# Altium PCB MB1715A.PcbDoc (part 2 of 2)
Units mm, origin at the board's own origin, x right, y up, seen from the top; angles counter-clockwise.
Board outline 74 x 57 mm, 2 copper layers (Top Layer, Bottom Layer), stack 1.646 mm thick; 54 components, 56 nets, 204 pads, 1587 vias.
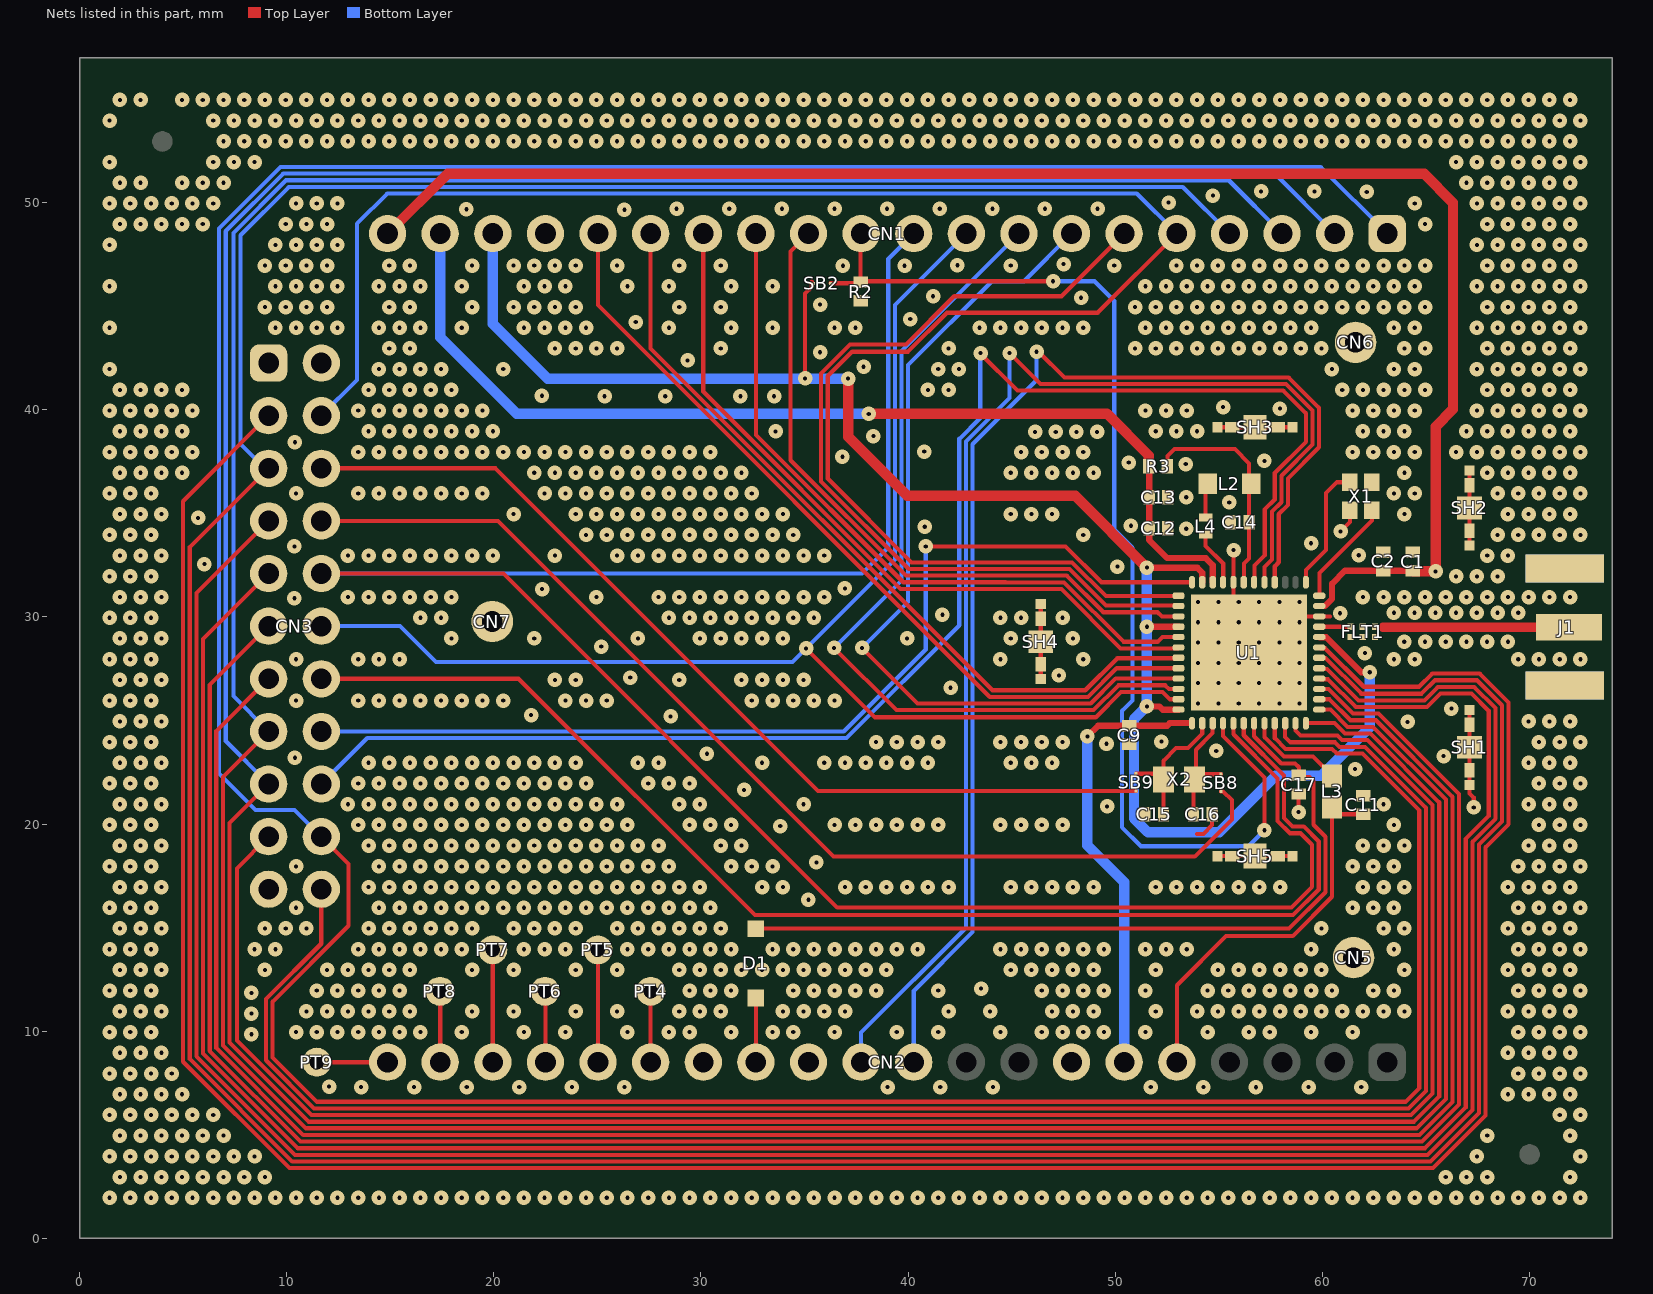
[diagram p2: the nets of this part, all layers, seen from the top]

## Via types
v1: diameter 0.7, hole 0.2, Top Layer to Bottom Layer, 1587 vias

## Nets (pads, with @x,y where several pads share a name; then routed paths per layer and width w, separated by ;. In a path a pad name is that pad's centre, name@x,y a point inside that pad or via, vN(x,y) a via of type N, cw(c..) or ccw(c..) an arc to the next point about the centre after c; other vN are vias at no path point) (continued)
GND: C1.1 C2.1 C9.1 C11.1 C12.2 C13.1 C14.2 C15.2 C16.2 C17.1 CN1.17 CN2.7 CN2.12 CN2.14 CN3.1 CN3.2 CN3.21 CN5.1 CN6.1 CN7.1 FLT1.1 FLT1.2 FLT1.3 FLT1.4 J1.2 R2.2 SH1.1 SH2.1 SH3.1 SH4.1 SH5.1 U1.22 U1.32 U1.49 X1.2 X1.4 | length 32.7
  Top Layer w0.2: SH4.1@46.4,26.99 SH4.1@46.4,27.7 SH4.1@46.4,28.8 SH4.1@46.4,29.9 SH4.1@46.4,30.61 ; 53.95,19.525 54.25,19.525 54.675,19.95 C16.2@54.675,20.475 ; SH5.1@54.94,18.45 SH5.1@56.75,18.45 SH5.1@58.56,18.45 ; SH3.1@54.94,39.15 SH3.1@56.75,39.15 SH3.1@58.56,39.15 ; U1.32@55.7,31.669 55.7,29.032 56.461,28.27 58.21,30.019 60.36,30.019 ; U1.32@55.712,31.669 v1(55.712,33.22) ; v1(58.85,20.575) C17.1@58.85,21.45 ; v1(60.875,34.125) 61.325,34.575 X1.2@61.325,35.15 ; SH1.1@67.1,25.51 SH1.1@67.1,24.8 SH1.1@67.1,23.7 SH1.1@67.1,22.6 SH1.1@67.1,21.89 67.1,21.475 67.3,21.275 v1(67.3,20.8) ; SH2.1@67.1,33.45 SH2.1@67.1,34.16 SH2.1@67.1,35.26 SH2.1@67.1,36.36 SH2.1@67.1,37.07
  other v1: 1.452,1.956 2.452,1.956 3.452,1.956 4.452,1.956 5.452,1.956 6.452,1.956 7.452,1.956 8.452,1.956 9.452,1.956 10.452,1.956 11.452,1.956 12.452,1.956 13.452,1.956 14.452,1.956 15.452,1.956 16.452,1.956 17.452,1.956 18.452,1.956 19.452,1.956 20.452,1.956 21.452,1.956 22.452,1.956 23.452,1.956 24.452,1.956 25.452,1.956 26.452,1.956 27.452,1.956 28.452,1.956 29.452,1.956 30.452,1.956 31.452,1.956 32.452,1.956 33.452,1.956 34.452,1.956 35.452,1.956 36.452,1.956 37.452,1.956 38.452,1.956 39.452,1.956 40.452,1.956 41.452,1.956 42.452,1.956 43.452,1.956 44.452,1.956 45.452,1.956 46.452,1.956 47.452,1.956 48.452,1.956 49.452,1.956 50.452,1.956 51.452,1.956 52.452,1.956 53.452,1.956 54.452,1.956 55.452,1.956 56.452,1.956 57.452,1.956 58.452,1.956 59.452,1.956 60.452,1.956 61.452,1.956 62.452,1.956 63.452,1.956 64.452,1.956 65.452,1.956 66.452,1.956 67.452,1.956 68.452,1.956 69.452,1.956 70.452,1.956 71.452,1.956 72.452,1.956 1.952,2.956 2.952,2.956 3.952,2.956 4.952,2.956 5.952,2.956 6.952,2.956 7.952,2.956 8.952,2.956 65.952,2.956 66.952,2.956 67.952,2.956 71.952,2.956 1.452,3.956 2.452,3.956 3.452,3.956 4.452,3.956 5.452,3.956 6.452,3.956 7.452,3.956 8.452,3.956 67.452,3.956 72.452,3.956 1.952,4.956 2.952,4.956 3.952,4.956 4.952,4.956 5.952,4.956 6.952,4.956 67.952,4.956 71.952,4.956 1.452,5.956 2.452,5.956 3.452,5.956 4.452,5.956 5.452,5.956 6.452,5.956 71.452,5.956 72.452,5.956 1.952,6.956 2.952,6.956 3.952,6.956 4.952,6.956 68.952,6.956 69.952,6.956 70.952,6.956 71.952,6.956 13.59,7.3 16.15,7.3 18.69,7.3 21.23,7.3 23.77,7.3 26.308,7.298 39.01,7.3 41.55,7.3 44.09,7.3 51.71,7.3 54.25,7.3 56.785,7.295 59.33,7.3 61.87,7.3 12.05,7.325 1.452,7.956 2.452,7.956 3.452,7.956 4.452,7.956 69.452,7.956 70.452,7.956 71.452,7.956 72.452,7.956 1.952,8.956 2.952,8.956 3.952,8.956 68.952,8.956 69.952,8.956 70.952,8.956 71.952,8.956 8.3,9.85 1.452,9.956 2.452,9.956 3.452,9.956 10.452,9.956 11.452,9.956 12.452,9.956 13.452,9.956 14.452,9.956 15.452,9.956 16.452,9.956 18.452,9.956 21.452,9.956 23.452,9.956 26.452,9.956 28.452,9.956 29.452,9.956 31.452,9.956 33.452,9.956 34.452,9.956 36.452,9.956 39.452,9.956 41.452,9.956 44.452,9.956 46.452,9.956 47.452,9.956 48.452,9.956 49.452,9.956 51.452,9.956 54.452,9.956 56.452,9.956 57.452,9.956 59.452,9.956 61.452,9.956 69.452,9.956 70.452,9.956 71.452,9.956 72.452,9.956 8.3,10.85 1.952,10.956 2.952,10.956 3.952,10.956 10.952,10.956 11.952,10.956 12.952,10.956 13.952,10.956 14.952,10.956 15.952,10.956 18.952,10.956 20.952,10.956 23.952,10.956 25.952,10.956 28.952,10.956 29.952,10.956 30.952,10.956 33.952,10.956 34.952,10.956 35.952,10.956 36.952,10.956 41.952,10.956 43.952,10.956 46.952,10.956 47.952,10.956 48.952,10.956 51.952,10.956 53.952,10.956 54.952,10.956 55.952,10.956 56.952,10.956 57.952,10.956 58.952,10.956 59.952,10.956 60.952,10.956 61.952,10.956 62.952,10.956 63.952,10.956 68.952,10.956 69.952,10.956 70.952,10.956 71.952,10.956 8.3,11.85 1.452,11.956 2.452,11.956 3.452,11.956 11.452,11.956 12.452,11.956 13.452,11.956 14.452,11.956 15.452,11.956 29.452,11.956 30.452,11.956 31.452,11.956 34.452,11.956 35.452,11.956 36.452,11.956 37.452,11.956 38.452,11.956 41.452,11.956 46.452,11.956 47.452,11.956 48.452,11.956 49.452,11.956 51.452,11.956 54.452,11.956 55.452,11.956 56.452,11.956 57.452,11.956 58.452,11.956 59.452,11.956 60.452,11.956 62.452,11.956 63.452,11.956 69.452,11.956 70.452,11.956 71.452,11.956 72.452,11.956 43.518,12.057 1.952,12.956 2.952,12.956 3.952,12.956 8.952,12.956 11.952,12.956 12.952,12.956 13.952,12.956 14.952,12.956 15.952,12.956 18.952,12.956 20.952,12.956 23.952,12.956 25.952,12.956 28.952,12.956 29.952,12.956 30.952,12.956 31.952,12.956 32.952,12.956 33.952,12.956 34.952,12.956 35.952,12.956 36.952,12.956 37.952,12.956 38.952,12.956 44.952,12.956 45.952,12.956 46.952,12.956 47.952,12.956 48.952,12.956 51.952,12.956 54.952,12.956 55.952,12.956 56.952,12.956 57.952,12.956 58.952,12.956 59.952,12.956 63.952,12.956 68.952,12.956 69.952,12.956 70.952,12.956 71.952,12.956 1.452,13.956 2.452,13.956 3.452,13.956 8.452,13.956 9.452,13.956 13.452,13.956 14.452,13.956 15.452,13.956 16.452,13.956 17.452,13.956 18.452,13.956 21.452,13.956 22.452,13.956 23.452,13.956 26.452,13.956 27.452,13.956 28.452,13.956 29.452,13.956 30.452,13.956 31.452,13.956 33.452,13.956 34.452,13.956 35.452,13.956 36.452,13.956 37.452,13.956 38.452,13.956 39.452,13.956 40.452,13.956 44.452,13.956 45.452,13.956 46.452,13.956 47.452,13.956 48.452,13.956 49.452,13.956 51.452,13.956 52.452,13.956 53.452,13.956 59.452,13.956 63.452,13.956 69.452,13.956 70.452,13.956 71.452,13.956 72.452,13.956 1.952,14.956 2.952,14.956 3.952,14.956 8.952,14.956 9.952,14.956 10.952,14.956 13.952,14.956 14.952,14.956 15.952,14.956 16.952,14.956 17.952,14.956 18.952,14.956 20.952,14.956 21.952,14.956 22.952,14.956 23.952,14.956 25.952,14.956 26.952,14.956 27.952,14.956 28.952,14.956 29.952,14.956 30.952,14.956 59.952,14.956 62.952,14.956 63.952,14.956 68.952,14.956 69.952,14.956 70.952,14.956 71.952,14.956 1.452,15.956 2.452,15.956 3.452,15.956 10.452,15.956 14.452,15.956 15.452,15.956 16.452,15.956 17.452,15.956 18.452,15.956 19.452,15.956 20.452,15.956 21.452,15.956 22.452,15.956 23.452,15.956 24.452,15.956 25.452,15.956 26.452,15.956 27.452,15.956 28.452,15.956 29.452,15.956 30.452,15.956 61.452,15.956 62.452,15.956 63.452,15.956 69.452,15.956 70.452,15.956 71.452,15.956 72.452,15.956 35.182,16.343 1.952,16.956 2.952,16.956 3.952,16.956 13.952,16.956 14.952,16.956 15.952,16.956 16.952,16.956 17.952,16.956 18.952,16.956 19.952,16.956 20.952,16.956 21.952,16.956 22.952,16.956 23.952,16.956 24.952,16.956 25.952,16.956 26.952,16.956 27.952,16.956 28.952,16.956 29.952,16.956 32.952,16.956 33.952,16.956 36.952,16.956 37.952,16.956 38.952,16.956 39.952,16.956 40.952,16.956 41.952,16.956 44.952,16.956 45.952,16.956 46.952,16.956 47.952,16.956 48.952,16.956 51.952,16.956 52.952,16.956 53.952,16.956 54.952,16.956 55.952,16.956 56.952,16.956 57.952,16.956 61.952,16.956 62.952,16.956 63.952,16.956 68.952,16.956 69.952,16.956 70.952,16.956 71.952,16.956 1.452,17.956 2.452,17.956 3.452,17.956 10.452,17.956 14.452,17.956 15.452,17.956 16.452,17.956 17.452,17.956 18.452,17.956 19.452,17.956 20.452,17.956 21.452,17.956 22.452,17.956 23.452,17.956 24.452,17.956 25.452,17.956 26.452,17.956 27.452,17.956 28.452,17.956 31.452,17.956 32.452,17.956 33.452,17.956 61.452,17.956 62.452,17.956 63.452,17.956 69.452,17.956 70.452,17.956 71.452,17.956 72.452,17.956 35.575,18.15 1.952,18.956 2.952,18.956 3.952,18.956 13.952,18.956 14.952,18.956 15.952,18.956 16.952,18.956 17.952,18.956 18.952,18.956 19.952,18.956 20.952,18.956 21.952,18.956 22.952,18.956 23.952,18.956 24.952,18.956 25.952,18.956 26.952,18.956 27.952,18.956 30.952,18.956 31.952,18.956 61.952,18.956 62.952,18.956 63.952,18.956 69.952,18.956 70.952,18.956 71.952,18.956 33.825,19.9 1.452,19.956 2.452,19.956 3.452,19.956 13.452,19.956 14.452,19.956 15.452,19.956 16.452,19.956 17.452,19.956 18.452,19.956 19.452,19.956 20.452,19.956 21.452,19.956 22.452,19.956 23.452,19.956 24.452,19.956 25.452,19.956 26.452,19.956 29.452,19.956 30.452,19.956 31.452,19.956 36.452,19.956 37.452,19.956 38.452,19.956 39.452,19.956 40.452,19.956 41.452,19.956 44.452,19.956 45.452,19.956 46.452,19.956 47.452,19.956 63.452,19.956 70.452,19.956 71.452,19.956 72.452,19.956 49.6,20.85 1.952,20.956 2.952,20.956 3.952,20.956 12.952,20.956 13.952,20.956 14.952,20.956 15.952,20.956 16.952,20.956 17.952,20.956 18.952,20.956 19.952,20.956 20.952,20.956 21.952,20.956 22.952,20.956 23.952,20.956 24.952,20.956 25.952,20.956 28.952,20.956 29.952,20.956 34.952,20.956 62.952,20.956 69.952,20.956 70.952,20.956 71.952,20.956 32.082,21.643 1.452,21.956 2.452,21.956 3.452,21.956 13.452,21.956 14.452,21.956 15.452,21.956 16.452,21.956 17.452,21.956 18.452,21.956 19.452,21.956 20.452,21.956 21.452,21.956 22.452,21.956 23.452,21.956 24.452,21.956 27.452,21.956 28.452,21.956 29.452,21.956 70.452,21.956 71.452,21.956 72.452,21.956 61.575,22.65 1.952,22.956 2.952,22.956 3.952,22.956 13.952,22.956 14.952,22.956 15.952,22.956 16.952,22.956 17.952,22.956 18.952,22.956 19.952,22.956 20.952,22.956 21.952,22.956 22.952,22.956 23.952,22.956 26.952,22.956 27.952,22.956 32.952,22.956 35.952,22.956 36.952,22.956 37.952,22.956 38.952,22.956 39.952,22.956 40.952,22.956 44.952,22.956 45.952,22.956 46.952,22.956 69.952,22.956 70.952,22.956 71.952,22.956 10.4,23.2 65.85,23.275 30.282,23.393 54.875,23.525 49.575,23.875 1.452,23.956 2.452,23.956 3.452,23.956 38.452,23.956 39.452,23.956 40.452,23.956 41.452,23.956 44.452,23.956 45.452,23.956 46.452,23.956 47.452,23.956 70.452,23.956 71.452,23.956 72.452,23.956 52.225,23.975 64.11,24.931 1.952,24.956 2.952,24.956 3.952,24.956 69.952,24.956 70.952,24.956 71.952,24.956 28.532,25.193 21.801,25.26 66.225,25.575 54,25.82 54.98,25.82 55.96,25.82 56.94,25.82 57.92,25.82 58.9,25.82 1.452,25.956 2.452,25.956 3.452,25.956 10.452,25.956 13.452,25.956 14.452,25.956 15.452,25.956 16.452,25.956 17.452,25.956 18.452,25.956 19.452,25.956 20.452,25.956 23.452,25.956 24.452,25.956 25.452,25.956 32.452,25.956 33.452,25.956 34.452,25.956 35.452,25.956 36.452,25.956 42.05,26.575 54,26.8 54.98,26.8 55.96,26.8 56.94,26.8 57.92,26.8 58.9,26.8 1.952,26.956 2.952,26.956 3.952,26.956 22.952,26.956 23.952,26.956 28.952,26.956 31.952,26.956 32.952,26.956 33.952,26.956 34.952,26.956 26.582,27.068 47.275,27.175 54,27.78 54.98,27.78 55.96,27.78 56.94,27.78 57.92,27.78 58.9,27.78 1.452,27.956 2.452,27.956 3.452,27.956 10.452,27.956 13.452,27.956 14.452,27.956 15.452,27.956 44.452,27.956 48.452,27.956 63.452,27.956 64.452,27.956 69.452,27.956 70.452,27.956 71.452,27.956 72.452,27.956 62.05,28.25 25.182,28.568 54,28.76 54.98,28.76 55.96,28.76 56.94,28.76 57.92,28.76 58.9,28.76 63.95,28.8 64.95,28.8 65.95,28.8 66.95,28.8 67.95,28.8 68.95,28.8 1.952,28.956 2.952,28.956 3.952,28.956 17.952,28.956 21.952,28.956 26.952,28.956 29.952,28.956 30.952,28.956 31.952,28.956 32.952,28.956 33.952,28.956 39.952,28.956 44.952,28.956 47.952,28.956 54,29.74 54.98,29.74 55.96,29.74 56.94,29.74 57.92,29.74 58.9,29.74 1.452,29.956 2.452,29.956 3.452,29.956 16.452,29.956 17.452,29.956 28.452,29.956 29.452,29.956 30.452,29.956 31.452,29.956 32.452,29.956 33.452,29.956 34.452,29.956 35.452,29.956 44.452,29.956 45.452,29.956 47.452,29.956 41.65,30.1 60.85,30.175 63.45,30.2 64.45,30.2 65.45,30.2 66.45,30.2 67.45,30.2 68.45,30.2 69.45,30.2 54,30.72 54.98,30.72 55.96,30.72 56.94,30.72 57.92,30.72 58.9,30.72 10.375,30.9 1.952,30.956 2.952,30.956 3.952,30.956 12.952,30.956 13.952,30.956 14.952,30.956 15.952,30.956 16.952,30.956 17.952,30.956 24.952,30.956 27.952,30.956 28.952,30.956 29.952,30.956 30.952,30.956 31.952,30.956 32.952,30.956 33.952,30.956 34.952,30.956 35.952,30.956 61.952,30.956 62.952,30.956 63.952,30.956 64.952,30.956 65.952,30.956 66.952,30.956 67.952,30.956 68.952,30.956 69.952,30.956 70.952,30.956 71.952,30.956 22.332,31.343 36.95,31.375 1.452,31.956 2.452,31.956 3.452,31.956 66.452,31.956 67.452,31.956 68.452,31.956 50.1,32.425 6.025,32.55 1.952,32.956 2.952,32.956 3.952,32.956 12.952,32.956 13.952,32.956 14.952,32.956 15.952,32.956 16.952,32.956 17.952,32.956 18.952,32.956 19.952,32.956 22.952,32.956 25.952,32.956 26.952,32.956 27.952,32.956 28.952,32.956 29.952,32.956 30.952,32.956 31.952,32.956 32.952,32.956 33.952,32.956 34.952,32.956 35.952,32.956 61.75,32.975 67.952,32.956 68.952,32.956 10.375,33.4 59.45,33.55 1.452,33.956 2.452,33.956 3.452,33.956 24.452,33.956 25.452,33.956 26.452,33.956 27.452,33.956 28.452,33.956 29.452,33.956 30.452,33.956 31.452,33.956 32.452,33.956 33.452,33.956 34.452,33.956 48.452,33.956 68.452,33.956 69.452,33.956 70.452,33.956 71.452,33.956 72.452,33.956 53.425,34.25 40.8,34.35 50.75,34.4 5.725,34.775 1.952,34.956 2.952,34.956 3.952,34.956 20.952,34.956 23.952,34.956 24.952,34.956 25.952,34.956 26.952,34.956 27.952,34.956 28.952,34.956 29.952,34.956 30.952,34.956 31.952,34.956 32.952,34.956 33.952,34.956 44.952,34.956 45.952,34.956 46.952,34.956 63.952,34.956 68.952,34.956 69.952,34.956 70.952,34.956 71.952,34.956 55.5,35.525 53.425,35.775 1.452,35.956 2.452,35.956 3.452,35.956 10.452,35.956 13.452,35.956 14.452,35.956 15.452,35.956 16.452,35.956 17.452,35.956 18.452,35.956 19.452,35.956 22.452,35.956 23.452,35.956 24.452,35.956 25.452,35.956 26.452,35.956 27.452,35.956 28.452,35.956 29.452,35.956 30.452,35.956 31.452,35.956 32.452,35.956 63.452,35.956 64.452,35.956 68.452,35.956 69.452,35.956 70.452,35.956 71.452,35.956 72.452,35.956 1.952,36.956 2.952,36.956 3.952,36.956 4.952,36.956 21.952,36.956 22.952,36.956 23.952,36.956 24.952,36.956 25.952,36.956 26.952,36.956 27.952,36.956 28.952,36.956 29.952,36.956 30.952,36.956 31.952,36.956 44.952,36.956 45.952,36.956 46.952,36.956 47.952,36.956 48.952,36.956 63.952,36.956 67.952,36.956 68.952,36.956 69.952,36.956 70.952,36.956 71.952,36.956 53.4,37.375 50.65,37.45 57.2,37.525 36.825,37.725 1.452,37.956 2.452,37.956 3.452,37.956 4.452,37.956 5.452,37.956 13.452,37.956 14.452,37.956 15.452,37.956 16.452,37.956 17.452,37.956 18.452,37.956 19.452,37.956 20.452,37.956 21.452,37.956 22.452,37.956 23.452,37.956 24.452,37.956 25.452,37.956 26.452,37.956 27.452,37.956 28.452,37.956 29.452,37.956 30.452,37.956 45.452,37.956 46.452,37.956 47.452,37.956 48.452,37.956 61.452,37.956 62.452,37.956 63.452,37.956 64.452,37.956 66.452,37.956 67.452,37.956 68.452,37.956 69.452,37.956 70.452,37.956 71.452,37.956 72.452,37.956 40.775,37.975 10.4,38.425 38.325,38.725 33.6,38.95 46.125,38.925 47.125,38.925 48.125,38.925 49.125,38.925 1.952,38.956 2.952,38.956 3.952,38.956 4.952,38.956 13.952,38.956 14.952,38.956 15.952,38.956 16.952,38.956 17.952,38.956 18.952,38.956 19.952,38.956 51.952,38.956 52.952,38.956 53.952,38.956 61.952,38.956 62.952,38.956 63.952,38.956 66.952,38.956 67.952,38.956 68.952,38.956 69.952,38.956 70.952,38.956 71.952,38.956 1.452,39.956 2.452,39.956 3.452,39.956 4.452,39.956 5.452,39.956 13.452,39.956 14.452,39.956 15.452,39.956 16.452,39.956 17.452,39.956 18.452,39.956 19.452,39.956 51.452,39.956 52.452,39.956 53.452,39.956 61.452,39.956 62.452,39.956 63.452,39.956 64.452,39.956 67.452,39.956 68.452,39.956 69.452,39.956 70.452,39.956 71.452,39.956 72.452,39.956 57.95,40.05 55.2,40.125 25.35,40.65 28.275,40.65 31.9,40.65 33.525,40.65 22.325,40.675 1.952,40.956 2.952,40.956 3.952,40.956 4.952,40.956 13.952,40.956 14.952,40.956 15.952,40.956 16.952,40.956 17.952,40.956 40.952,40.956 41.952,40.956 60.952,40.956 61.952,40.956 62.952,40.956 63.952,40.956 64.952,40.956 67.952,40.956 68.952,40.956 69.952,40.956 70.952,40.956 71.952,40.956 1.452,41.956 14.452,41.956 15.452,41.956 16.452,41.956 17.452,41.956 20.452,41.956 41.452,41.956 42.452,41.956 60.452,41.956 63.452,41.956 64.452,41.956 67.452,41.956 68.452,41.956 69.452,41.956 70.452,41.956 71.452,41.956 72.452,41.956 37.85,42.075 29.35,42.375 35.75,42.775 14.952,42.956 15.952,42.956 22.952,42.956 23.952,42.956 24.952,42.956 25.952,42.956 30.952,42.956 41.952,42.956 50.952,42.956 51.952,42.956 52.952,42.956 53.952,42.956 54.952,42.956 55.952,42.956 56.952,42.956 57.952,42.956 58.952,42.956 59.952,42.956 63.952,42.956 64.952,42.956 67.952,42.956 68.952,42.956 69.952,42.956 70.952,42.956 71.952,42.956 1.452,43.956 9.452,43.956 10.452,43.956 11.452,43.956 12.452,43.956 14.452,43.956 15.452,43.956 16.452,43.956 18.452,43.956 21.452,43.956 22.452,43.956 23.452,43.956 24.452,43.956 28.452,43.956 31.452,43.956 33.452,43.956 36.452,43.956 37.452,43.956 43.452,43.956 44.452,43.956 45.452,43.956 46.452,43.956 47.452,43.956 48.452,43.956 51.452,43.956 52.452,43.956 53.452,43.956 54.452,43.956 55.452,43.956 56.452,43.956 57.452,43.956 58.452,43.956 59.452,43.956 63.452,43.956 64.452,43.956 67.452,43.956 68.452,43.956 69.452,43.956 70.452,43.956 71.452,43.956 72.452,43.956 26.85,44.225 40.1,44.375 8.952,44.956 9.952,44.956 10.952,44.956 11.952,44.956 14.952,44.956 15.952,44.956 18.952,44.956 20.952,44.956 21.952,44.956 22.952,44.956 23.952,44.956 28.952,44.956 30.952,44.956 50.952,44.956 51.952,44.956 52.952,44.956 53.952,44.956 54.952,44.956 55.952,44.956 56.952,44.956 57.952,44.956 58.952,44.956 59.952,44.956 60.952,44.956 61.952,44.956 62.952,44.956 63.952,44.956 64.952,44.956 67.952,44.956 68.952,44.956 69.952,44.956 70.952,44.956 71.952,44.956 35.75,45.075 48.35,45.4 41.2,45.475 1.452,45.956 9.452,45.956 10.452,45.956 11.452,45.956 12.452,45.956 14.452,45.956 15.452,45.956 16.452,45.956 18.452,45.956 21.452,45.956 22.452,45.956 23.452,45.956 26.452,45.956 28.452,45.956 31.452,45.956 33.452,45.956 51.452,45.956 52.452,45.956 53.452,45.956 54.452,45.956 55.452,45.956 56.452,45.956 57.452,45.956 58.452,45.956 59.452,45.956 60.452,45.956 61.452,45.956 62.452,45.956 63.452,45.956 64.452,45.956 67.452,45.956 68.452,45.956 69.452,45.956 70.452,45.956 71.452,45.956 72.452,45.956 36.85,46.95 39.825,46.95 8.952,46.956 9.952,46.956 10.952,46.956 11.952,46.956 14.952,46.956 15.952,46.956 18.952,46.956 20.952,46.956 21.952,46.956 22.952,46.956 23.952,46.956 25.952,46.956 28.952,46.956 30.952,46.956 42.375,46.975 44.952,46.956 49.952,46.956 52.952,46.956 53.952,46.956 54.952,46.956 55.952,46.956 56.952,46.956 57.952,46.956 58.952,46.956 59.952,46.956 60.952,46.956 61.952,46.956 62.952,46.956 63.952,46.956 64.952,46.956 67.952,46.956 68.952,46.956 69.952,46.956 70.952,46.956 71.952,46.956 47.5,47.025 1.452,47.956 9.452,47.956 10.452,47.956 11.452,47.956 12.452,47.956 67.452,47.956 68.452,47.956 69.452,47.956 70.452,47.956 71.452,47.956 72.452,47.956 1.952,48.956 2.952,48.956 3.952,48.956 4.952,48.956 5.952,48.956 9.952,48.956 10.952,48.956 11.952,48.956 64.952,48.956 67.952,48.956 68.952,48.956 69.952,48.956 70.952,48.956 71.952,48.956 26.3,49.65 18.675,49.675 28.825,49.7 31.365,49.7 33.905,49.7 36.445,49.7 38.985,49.7 41.525,49.7 44.065,49.7 46.605,49.7 49.145,49.7 1.452,49.956 2.452,49.956 3.452,49.956 4.452,49.956 5.452,49.956 6.452,49.956 10.452,49.956 11.452,49.956 12.452,49.956 64.452,49.956 67.452,49.956 68.452,49.956 69.452,49.956 70.452,49.956 71.452,49.956 72.452,49.956 52.575,50 54.71,50.335 62.135,50.51 57.035,50.535 59.61,50.535 1.952,50.956 2.952,50.956 4.952,50.956 5.952,50.956 6.952,50.956 66.952,50.956 67.952,50.956 68.952,50.956 69.952,50.956 70.952,50.956 71.952,50.956 1.452,51.956 6.452,51.956 7.452,51.956 8.452,51.956 66.452,51.956 67.452,51.956 68.452,51.956 69.452,51.956 70.452,51.956 71.452,51.956 72.452,51.956 6.952,52.956 7.952,52.956 8.952,52.956 9.952,52.956 10.952,52.956 11.952,52.956 12.952,52.956 13.952,52.956 14.952,52.956 15.952,52.956 16.952,52.956 17.952,52.956 18.952,52.956 19.952,52.956 20.952,52.956 21.952,52.956 22.952,52.956 23.952,52.956 24.952,52.956 25.952,52.956 26.952,52.956 27.952,52.956 28.952,52.956 29.952,52.956 30.952,52.956 31.952,52.956 32.952,52.956 33.952,52.956 34.952,52.956 35.952,52.956 36.952,52.956 37.952,52.956 38.952,52.956 39.952,52.956 40.952,52.956 41.952,52.956 42.952,52.956 43.952,52.956 44.952,52.956 45.952,52.956 46.952,52.956 47.952,52.956 48.952,52.956 49.952,52.956 50.952,52.956 51.952,52.956 52.952,52.956 53.952,52.956 54.952,52.956 55.952,52.956 56.952,52.956 57.952,52.956 58.952,52.956 59.952,52.956 60.952,52.956 61.952,52.956 62.952,52.956 63.952,52.956 64.952,52.956 65.952,52.956 66.952,52.956 67.952,52.956 68.952,52.956 69.952,52.956 70.952,52.956 71.952,52.956 1.452,53.956 6.452,53.956 7.452,53.956 8.452,53.956 9.452,53.956 10.452,53.956 11.452,53.956 12.452,53.956 13.452,53.956 14.452,53.956 15.452,53.956 16.452,53.956 17.452,53.956 18.452,53.956 19.452,53.956 20.452,53.956 21.452,53.956 22.452,53.956 23.452,53.956 24.452,53.956 25.452,53.956 26.452,53.956 27.452,53.956 28.452,53.956 29.452,53.956 30.452,53.956 31.452,53.956 32.452,53.956 33.452,53.956 34.452,53.956 35.452,53.956 36.452,53.956 37.452,53.956 38.452,53.956 39.452,53.956 40.452,53.956 41.452,53.956 42.452,53.956 43.452,53.956 44.452,53.956 45.452,53.956 46.452,53.956 47.452,53.956 48.452,53.956 49.452,53.956 50.452,53.956 51.452,53.956 52.452,53.956 53.452,53.956 54.452,53.956 55.452,53.956 56.452,53.956 57.452,53.956 58.452,53.956 59.452,53.956 60.452,53.956 61.452,53.956 62.452,53.956 63.452,53.956 64.452,53.956 65.452,53.956 66.452,53.956 67.452,53.956 68.452,53.956 69.452,53.956 70.452,53.956 71.452,53.956 72.452,53.956 1.952,54.956 2.952,54.956 4.952,54.956 5.952,54.956 6.952,54.956 7.952,54.956 8.952,54.956 9.952,54.956 10.952,54.956 11.952,54.956 12.952,54.956 13.952,54.956 14.952,54.956 15.952,54.956 16.952,54.956 17.952,54.956 18.952,54.956 19.952,54.956 20.952,54.956 21.952,54.956 22.952,54.956 23.952,54.956 24.952,54.956 25.952,54.956 26.952,54.956 27.952,54.956 28.952,54.956 29.952,54.956 30.952,54.956 31.952,54.956 32.952,54.956 33.952,54.956 34.952,54.956 35.952,54.956 36.952,54.956 37.952,54.956 38.952,54.956 39.952,54.956 40.952,54.956 41.952,54.956 42.952,54.956 43.952,54.956 44.952,54.956 45.952,54.956 46.952,54.956 47.952,54.956 48.952,54.956 49.952,54.956 50.952,54.956 51.952,54.956 52.952,54.956 53.952,54.956 54.952,54.956 55.952,54.956 56.952,54.956 57.952,54.956 58.952,54.956 59.952,54.956 60.952,54.956 61.952,54.956 62.952,54.956 63.952,54.956 64.952,54.956 65.952,54.956 66.952,54.956 67.952,54.956 68.952,54.956 69.952,54.956 70.952,54.956 71.952,54.956
NetC14_1: C14.1 L2.2 R3.2 U1.31 | length 10.7
  Top Layer w0.2: R3.2@52.511,37.27 52.511,37.759 52.852,38.1 55.772,38.1 56.461,37.41 C14.1@56.461,34.57 56.461,32.82 56.212,32.571 U1.31@56.212,31.669
NetC15_1: C15.1 SB9.2 U1.2 X2.1 | length 6.5
  Top Layer w0.2: SB9.2@51,22.425 52.15,22.425 52.325,22.6 52.325,23.05 52.936,23.661 53.511,23.661 54.211,24.361 54.2,24.373 U1.2@54.2,24.872 ; C15.1@52.325,20.475 X2.1@52.325,22.15
NetC16_1: C16.1 SB8.2 U1.3 X2.2 | length 6
  Top Layer w0.2: C16.1@53.775,20.475 53.775,22.016 53.888,22.129 X2.2@53.888,22.461 ; U1.3@54.7,24.872 54.7,24.397 53.888,23.585 X2.2@53.888,22.461 ; SB8.2@55.1,22.4 53.949,22.4 X2.2@53.888,22.461
NetC17_2: C17.2 D1.A U1.7 | length 38.5
  Top Layer w0.2: D1.A@32.65,14.95 34.15,14.95 58.388,14.95 60.141,16.704 60.141,19.384 59.561,19.964 59.561,22.089 59.375,22.275 58.85,22.275 58.862,22.286 58.862,22.739 58.675,22.925 58.012,22.925 56.7,24.237 U1.7@56.7,24.872
NetCN2_15: CN2.15 PT4.1 | length 3.4
  Top Layer w0.2: CN2.15@27.57,8.5 PT4.1@27.57,11.92
NetCN2_16: CN2.16 PT5.1 | length 5.4
  Top Layer w0.2: CN2.16@25.025,8.495 CN2.16@25.03,8.5 ; CN2.16@25.025,8.505 PT5.1@25.025,13.925
NetCN2_17: CN2.17 PT6.1 | length 3.4
  Top Layer w0.2: CN2.17@22.49,8.5 PT6.1@22.49,11.91
NetCN2_18: CN2.18 PT7.1 | length 5.4
  Top Layer w0.2: CN2.18@19.95,8.5 PT7.1@19.95,13.925
NetCN2_19: CN2.19 PT8.1 | length 3.4
  Top Layer w0.2: CN2.19@17.41,8.5 PT8.1@17.41,11.915
NetCN2_20: CN2.20 PT9.1 | length 3.4
  Top Layer w0.2: PT9.1@11.455,8.5 CN2.20@14.87,8.5
NetFLT1_5: FLT1.5 U1.21 | length 1.5
  Top Layer w0.2: U1.21@59.86,29.52 FLT1.5@61.359,29.52
NetFLT1_6: FLT1.6 J1.1 | length 9
  Top Layer w0.45: 62.92,29.5 J1.1@71.9,29.5
NetL2_1: L2.1 L4.1 | length 1.7
  Top Layer w0.2: L4.1@54.361,34.795 54.361,36.32 L2.1@54.461,36.42
NetL3_2: L3.2 U1.8 | length 4.7
  Top Layer w0.2: U1.8@57.2,24.872 57.2,24.19 58.139,23.25 59.55,23.25 60.461,22.339 L3.2@60.461,22.32
NetL4_2: L4.2 U1.33 | length 2.7
  Top Layer w0.2: L4.2@54.361,33.97 54.361,33.42 55.212,32.57 U1.33@55.212,31.669
NetU1_24: U1.24 X1.3 | length 5.2
  Top Layer w0.2: U1.24@59.86,31.019 59.86,32.119 62.386,34.645 X1.3@62.386,35.15
NetU1_25: U1.25 X1.1 | length 6.1
  Top Layer w0.2: U1.25@59.2,31.669 59.2,32.259 60.175,33.234 60.175,35.975 60.7,36.5 X1.1@61.325,36.5
NRST: CN2.13 D1.K | length 3.1
  Top Layer w0.2: CN2.13@32.65,8.5 D1.K@32.65,11.6
PA0: CN1.1 CN3.20 U1.9 | length 183.3
  Top Layer w0.2: CN3.20@11.67,19.39 12.993,18.067 12.993,15.09 9.32,11.417 9.32,8.73 11.46,6.59 64.015,6.59 64.675,7.25 64.675,20.65 61.925,23.4 60.692,23.4 60.468,23.624 58.218,23.624 57.7,24.142 U1.9@57.7,24.872
  Bottom Layer w0.2: CN3.20@11.67,19.39 10.385,20.675 8.5,20.675 6.738,22.437 6.738,48.749 9.705,51.715 59.915,51.715 CN1.1@63.13,48.5
PA1: CN3.22 U1.10 | length 89.2
  Top Layer w0.2: CN3.22@11.67,16.85 11.67,14.22 9,11.55 9,8.597 11.327,6.27 64.148,6.27 64.995,7.117 64.995,20.783 62.053,23.725 60.82,23.725 60.601,23.944 58.456,23.944 58.2,24.2 U1.10@58.2,24.872
PA2: CN3.19 U1.11 | length 92.5
  Top Layer w0.2: CN3.19@9.13,19.39 7.597,17.857 7.597,9.548 11.195,5.95 64.28,5.95 65.315,6.985 65.315,20.915 62.18,24.05 60.948,24.05 60.733,24.264 58.943,24.264 58.7,24.507 U1.11@58.7,24.872
PA3: CN1.2 CN3.17 U1.12 | length 179.4
  Top Layer w0.2: CN3.17@9.13,21.93 7.244,20.044 7.244,9.449 11.062,5.63 64.413,5.63 65.635,6.852 65.635,21.048 62.313,24.37 61.08,24.37 60.578,24.872 U1.12@59.222,24.872
  Bottom Layer w0.2: CN3.17@9.13,21.93 7.058,24.002 7.058,48.616 9.837,51.395 57.695,51.395 CN1.2@60.59,48.5
PA4: CN1.3 CN3.15 U1.13 | length 177.2
  Top Layer w0.2: CN3.15@9.13,24.47 6.924,22.264 6.924,9.316 10.93,5.31 64.545,5.31 65.955,6.72 65.955,21.18 62.445,24.69 61.213,24.69 60.384,25.519 U1.13@59.86,25.519
  Bottom Layer w0.2: CN3.15@9.13,24.47 7.425,26.175 7.425,48.53 9.97,51.075 55.475,51.075 CN1.3@58.05,48.5
PA5: CN3.13 U1.14 | length 104
  Top Layer w0.2: CN3.13@9.13,27.01 6.604,24.484 6.604,9.184 10.797,4.99 64.678,4.99 66.275,6.587 66.275,21.313 62.578,25.01 61.345,25.01 60.336,26.019 U1.14@59.86,26.019
PA6: CN3.11 U1.15 | length 108.4
  Top Layer w0.2: CN3.11@9.13,29.55 6.284,26.704 6.284,9.051 10.665,4.67 64.81,4.67 66.595,6.455 66.595,21.445 62.71,25.33 61.478,25.33 60.289,26.519 U1.15@59.86,26.519
PA7: CN3.9 U1.16 | length 117.1
  Top Layer w0.2: CN3.9@9.13,32.09 5.964,28.924 5.964,8.918 10.532,4.35 64.943,4.35 66.915,6.322 66.915,19.273 68.025,20.383 68.025,25.467 67.192,26.3 65.7,26.3 65.05,25.65 61.61,25.65 60.275,26.985 59.894,26.985 U1.16@59.86,27.019
PA8: CN3.7 U1.17 | length 121.4
  Top Layer w0.2: CN3.7@9.13,34.63 5.644,31.144 5.644,8.786 10.4,4.03 65.075,4.03 67.235,6.19 67.235,19.14 68.345,20.25 68.345,25.6 67.325,26.62 65.567,26.62 64.917,25.97 61.743,25.97 60.228,27.485 59.894,27.485 U1.17@59.86,27.519
PA9: CN1.4 CN3.5 U1.18 | length 187.3
  Top Layer w0.2: CN3.5@9.13,37.17 5.324,33.364 5.324,8.653 10.267,3.71 65.208,3.71 67.555,6.057 67.555,19.008 68.665,20.118 68.665,25.732 67.457,26.94 65.435,26.94 64.785,26.29 61.875,26.29 60.147,28.019 U1.18@59.86,28.019
  Bottom Layer w0.2: CN3.5@9.13,37.17 8.948,37.17 7.769,38.349 7.769,48.421 10.102,50.755 53.255,50.755 CN1.4@55.51,48.5
PA10: CN3.16 U1.36 | length 49.4
  Top Layer w0.2: v1(40.85,33.4) 45.35,33.4 47.601,33.4 49.332,31.669 U1.36@53.712,31.669
  Bottom Layer w0.2: CN3.16@11.67,24.47 36.892,24.47 40.85,28.428 v1(40.85,33.4)
PA11: CN1.5 CN3.4 U1.37 | length 94.9
  Top Layer w0.2: CN1.5@52.97,48.5 49.15,44.68 41.88,44.68 40,42.8 37.303,42.8 36.12,41.617 36.12,36.67 40.16,32.63 47.918,32.63 49.548,31 53.043,31 U1.37@53.063,31.02
  Bottom Layer w0.2: CN3.4@11.67,39.71 13.4,41.44 13.4,48.978 14.858,50.435 51.035,50.435 CN1.5@52.97,48.5
PA12: CN1.6 U1.38 | length 42.4
  Top Layer w0.2: CN1.6@50.43,48.5 47.405,45.475 42.222,45.475 39.894,43.147 37.197,43.147 35.8,41.75 35.8,36.538 40.028,32.31 47.786,32.31 49.553,30.542 U1.38@53.039,30.542 ; U1.38@53.063,30.519 U1.38@53.039,30.542 ; U1.38@53.063,30.521 53.042,30.542 U1.38@53.039,30.542
PA13-JTMS_SWDIO: CN1.12 U1.39 | length 33.2
  Top Layer w0.2: CN1.12@35.19,48.5 34.325,47.635 34.325,37.56 39.895,31.99 47.653,31.99 49.421,30.222 52.043,30.222 52.246,30.019 U1.39@53.063,30.019
PA14-JTCK_SWCLK: CN1.13 U1.41 | length 34.4
  Top Layer w0.2: CN1.13@32.65,48.5 32.65,38.783 39.763,31.67 44.705,31.67 44.714,31.661 47.529,31.661 50.391,28.8 52.052,28.8 52.273,29.021 U1.41@53.052,29.021 U1.41@53.063,29.021
PA15-JTDI: CN1.14 U1.42 | length 35.8
  Top Layer w0.2: CN1.14@30.11,48.5 30.11,40.87 39.639,31.341 47.397,31.341 50.258,28.48 53.023,28.48 U1.42@53.063,28.521 ; U1.42@53.024,28.48 U1.42@53.063,28.519
PB0/AT2: CN2.10 U1.28 | length 60.8
  Top Layer w0.2: v1(46.2,42.797) 46.303,42.797 47.54,41.56 58.37,41.56 59.84,40.09 59.84,38.185 58.335,36.68 58.335,35.399 57.892,34.956 57.892,32.634 57.7,32.443 U1.28@57.7,31.669
  Bottom Layer w0.2: CN2.10@40.27,8.5 40.27,11.94 43.11,14.78 43.11,38.33 46.2,41.42 v1(46.2,42.797)
PB1/AT3: CN2.11 U1.29 | length 62.2
  Top Layer w0.2: v1(44.9,42.735) 46.395,41.24 58.238,41.24 59.52,39.958 59.52,38.317 58.015,36.812 58.015,35.532 57.561,35.078 57.561,32.77 57.2,32.409 U1.29@57.2,31.669
  Bottom Layer w0.2: CN2.11@37.73,8.5 37.73,9.93 42.79,14.99 42.79,38.462 44.9,40.572 v1(44.9,42.735)
PB2: CN3.3 U1.19 | length 130.1
  Top Layer w0.2: CN3.3@9.13,39.71 5,35.58 5,8.525 10.135,3.39 65.34,3.39 67.875,5.925 67.875,18.875 68.985,19.985 68.985,25.865 67.59,27.26 65.302,27.26 64.667,26.625 61.993,26.625 60.133,28.485 59.894,28.485 U1.19@59.86,28.519
PB3-JTDO: CN1.15 U1.43 | length 38.5
  Top Layer w0.2: CN1.15@27.57,48.5 27.57,42.958 44.073,26.455 48.55,26.455 50.093,27.998 U1.43@53.041,27.998
PB4-NJTRST: CN1.16 U1.44 | length 39.9
  Top Layer w0.2: CN1.16@25.03,48.5 25.03,45.045 43.94,26.135 48.682,26.135 50.068,27.521 U1.44@53.052,27.521 U1.44@53.063,27.521
PB5: CN1.7 U1.45 | length 42
  Top Layer w0.2: v1(37.775,28.5) 40.46,25.815 48.815,25.815 50.019,27.019 53.061,27.019 U1.45@53.063,27.021
  Bottom Layer w0.2: v1(37.775,28.5) 40,30.725 40,42.159 44.041,46.2 45.59,46.2 CN1.7@47.89,48.5
PB6: CN1.8 U1.46 | length 42.1
  Top Layer w0.2: v1(36.425,28.5) 39.43,25.495 48.948,25.495 50.148,26.695 52.408,26.695 52.585,26.519 U1.46@53.063,26.519
  Bottom Layer w0.2: v1(36.425,28.5) 39.68,31.755 39.68,42.83 CN1.8@45.35,48.5
PB7: CN1.9 CN3.12 U1.47 | length 67.6
  Top Layer w0.2: v1(35.075,28.475) 38.4,25.15 49.055,25.15 50.28,26.375 52.275,26.375 52.632,26.019 U1.47@53.063,26.019
  Bottom Layer w0.2: CN3.12@11.67,29.55 15.475,29.55 17.2,27.825 34.425,27.825 v1(35.075,28.475) 39.36,32.76 39.36,45.05 CN1.9@42.81,48.5
PB8: CN1.10 CN3.10 U1.5 | length 108.2
  Top Layer w0.2: CN3.10@11.67,32.09 20.46,32.09 36.575,15.975 58.508,15.975 59.501,16.969 59.501,18.999 58.945,19.555 58.428,19.555 57.83,20.153 57.83,22.202 55.7,24.332 U1.5@55.7,24.872
  Bottom Layer w0.2: CN3.10@11.67,32.09 37.776,32.09 39.04,33.354 39.04,47.27 CN1.10@40.27,48.5
PB9: CN3.14 U1.6 | length 63.2
  Top Layer w0.2: CN3.14@11.67,27.01 21.19,27.01 32.6,15.6 50.553,15.6 58.585,15.6 59.821,16.836 59.821,19.154 59.1,19.875 58.56,19.875 58.15,20.285 58.15,22.334 56.2,24.285 U1.6@56.2,24.872
PC14: CN3.6 SB9.1 | length 45.8
  Top Layer w0.2: CN3.6@11.67,37.17 20.08,37.17 35.65,21.6 SB9.1@51,21.6
PC15: CN3.8 SB8.1 | length 53
  Top Layer w0.2: CN3.8@11.67,34.63 20.195,34.63 36.402,18.423 53.838,18.423 55.625,20.21 55.625,21.15 55.2,21.575 SB8.1@55.1,21.575
PE4: CN3.18 U1.30 | length 73.6
  Top Layer w0.2: v1@43.482,42.718 45.28,40.92 58.105,40.92 59.2,39.825 59.2,38.45 57.695,36.945 57.695,35.664 57.211,35.181 57.211,32.97 56.712,32.471 U1.30@56.712,31.669
  Bottom Layer w0.2: CN3.18@11.67,21.93 13.89,24.15 37.025,24.15 42.47,29.595 42.47,38.595 43.482,39.607 v1@43.482,42.718
  other v1: 43.5,42.735
PH3: CN1.11 R2.1 SB2.2 U1.4 | length 55.8
  Top Layer w0.2: SB2.2@36.25,46.1 37.65,46.1 R2.1@37.7,46.15 ; CN1.11@37.73,48.5 37.7,48.47 R2.1@37.7,46.15 ; v1@46.7,46.2 37.75,46.2 R2.1@37.7,46.15 ; U1.4@55.2,24.872 55.2,24.242 57.2,22.242 v1(57.2,19.7)
  Bottom Layer w0.2: v1(47,46.2) 49,46.2 49.95,45.25 49.95,34.21 50.825,33.335 50.825,25.965 50.325,25.465 50.325,19.84 51.24,18.925 56.425,18.925 v1(57.2,19.7)
VBAT: C9.2 CN2.6 U1.1 | length 21.8
  Top Layer w0.3: v1(48.65,24.225) 49.169,24.744 C9.2@50.661,24.744 52.503,24.744 52.631,24.872 U1.1@53.7,24.872
  Bottom Layer w0.5: v1(48.65,24.225) 48.65,18.975 50.43,17.195 CN2.6@50.43,8.5
VDD: CN1.18 SB2.1 U1.20 U1.35 U1.40 U1.48 | length 86
  Top Layer w0.2: CN1.18@19.95,48.5 CN1.18@19.95,48.976 ; v1(35.025,41.513) 35.025,45.6 35.35,45.925 35.35,46.175
  Top Layer w0.3: v1@51.525,25.67 52.14,25.67 52.291,25.519 U1.48@53.063,25.519 ; v1@51.525,32.37 53.961,32.37 54.2,32.132 U1.35@54.2,31.669 ; v1(51.527,29.519) U1.40@53.063,29.519 ; U1.20@59.86,29.019 60.181,29.019 61.875,27.325 v1@62.258,27.325
  Top Layer w0.5: v1(37.1,41.5) 37.1,38.687 39.947,35.84 48.06,35.84 v1(51.525,32.375)
  Bottom Layer w0.5: CN1.18@19.95,48.5 19.95,44.15 22.6,41.5 v1(37.1,41.5) ; v1(51.525,32.375) v1(51.525,25.675) 50.9,25.05 50.9,20.275 51.575,19.6 55.015,19.6 57.751,22.336 59.952,22.336 62.283,24.667 v1(62.283,27.325)
VDDA: C11.2 CN2.5 L3.1 | length 19
  Top Layer w0.2: CN2.5@52.97,8.5 52.97,12.216 55.347,14.593 58.568,14.593 60.461,16.486 L3.1@60.461,20.82 60.811,20.47 C11.2@61.961,20.47
VDDRF: C1.2 C2.2 CN1.20 U1.23 | length 78.1
  Top Layer w0.3: U1.23@59.86,30.519 60.117,30.519 60.461,30.863 60.461,31.595 61.087,32.22 C1.2@64.361,32.22
  Top Layer w0.5: CN1.20@14.87,48.5 14.875,48.505 17.765,51.395 64.905,51.395 66.3,50 66.3,40.025 65.461,39.186 v1(65.461,32.195) 64.386,32.195 C1.2@64.361,32.22 C1.2@64.374,32.22
VDDSMPS: C12.1 C13.2 CN1.19 R3.1 U1.34 | length 50.1
  Top Layer w0.3: R3.1@51.637,37.27 C13.2@51.637,35.77 C12.1@51.637,34.27 51.637,33.705 52.505,32.837 54.363,32.837 54.7,32.5 U1.34@54.7,31.669
  Top Layer w0.5: v1(38.1,39.8) 49.6,39.8 51.611,37.789 R3.1@51.611,37.27
  Bottom Layer w0.5: CN1.19@17.41,48.5 17.41,43.49 21.1,39.8 v1(38.1,39.8)
pads on no net: Cartridge.1 CARTRIDGE.1 CN2.1 CN2.2 CN2.3 CN2.4 Mire_1.1 MIRE_2.1
copper on no net: | length 0
  Bottom Layer w0.5: 55.5,8.49 55.51,8.5

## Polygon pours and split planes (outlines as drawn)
GND on Top Layer "GND_L01_P000" (solid, remove dead copper, pour order 0): 0,0.05 74,0.05 74,56.95 0,56.95
GND on Bottom Layer "GND_L02_P001" (solid, remove dead copper, pour order 1): 0,0.05 74,0.05 74,56.95 0,56.95

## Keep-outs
Keep-Out Layer:
  lines w1.2: 73.973,57 0,57 0,0 74,0 74,57

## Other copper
Top Layer:
  region net NetFLT1_6: 70.3,30.135 69.759,29.594 69.759,29.406 70.3,28.865 70.667,28.865 70.667,30.131 70.671,30.135
  pour cut-out: 59.736,31.545 59.736,24.995 53.186,24.995 53.186,31.545
  region: 60.924,29.795
  region net NetFLT1_6: 62.975,29.725 62.975,29.275 62.8,29.275 62.705,29.37 62.425,29.37 62.425,29.67 62.72,29.67 62.775,29.725

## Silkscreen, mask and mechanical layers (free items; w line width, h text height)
Top Overlay:
  text "GND" at 59.7,44.85 h2
  text "GND" at 17.975,26.925 h2
  text "GND" at 59.7,10.2 h2
Bottom Overlay:
  text "C" at 31.35,40.7 h10
  text "MB1715A" at 33.325,15.65 h2.5
Mechanical Drawing:
  lines w0.2: 37.6,82.452 156.6,82.453 ; 67.6,72.1 67.6,87.452 ; 80.564,95.147 91.193,95.147 111.75,95.147 130.222,95.147 145.395,95.147 157.458,95.147 ; 80.564,100.227 91.193,100.227 111.75,100.227 130.222,100.227 145.395,100.227 157.458,100.227 ; 80.564,105.307 91.193,105.307 111.75,105.307 130.222,105.307 145.395,105.307 157.458,105.307 ; 80.564,110.387 91.193,110.387 111.75,110.387 130.222,110.387 145.395,110.387 157.458,110.387 ; 80.564,115.467 91.193,115.467 111.75,115.467 130.222,115.467 145.395,115.467 157.458,115.467 ; 80.564,120.547 91.193,120.547 111.75,120.547 130.222,120.547 145.395,120.547 157.458,120.547 ; 80.564,125.627 157.458,125.627 ; 90.6,72.1 90.6,87.453 ; 91.193,130.707 91.193,90.067 ; 102.6,72.1 102.6,87.453 ; 111.75,130.707 111.75,90.067 ; 118.6,72.1 118.6,87.453 ; 130.222,130.707 130.222,90.067 ; 132.6,72.1 132.6,87.453 ; 144.6,72.1 144.6,87.453 ; 145.395,130.707 145.395,90.067 ; 91.193,90.067 80.564,90.067 80.564,130.707 157.458,130.707 157.458,90.067 145.395,90.067 ; 91.193,90.067 111.75,90.067 ; 111.75,90.067 130.222,90.067 ; 130.222,90.067 145.395,90.067 ; 37.6,72.1 37.6,87.452 156.6,87.453 156.6,72.1 37.6,72.1
  text "Layer" at 83.104,126.897 h2.54
  text "Name" at 93.733,126.897 h2.54
  text "Material" at 114.29,126.897 h2.54
  text "Thickness" at 132.762,126.897 h2.54
  text "Gerber" at 147.935,126.897 h2.54
  text "Top Overlay" at 93.733,121.817 h2.54
  text "GTO" at 147.935,121.817 h2.54
  text "Top Solder" at 93.733,116.737 h2.54
  text "Solder Resist" at 114.29,116.737 h2.54
  text "0.030mm" at 132.762,116.737 h2.54
  text "GTS" at 147.935,116.737 h2.54
  text "1" at 83.104,111.657 h2.54
  text "Top Layer" at 93.733,111.657 h2.54
  text "Copper" at 114.29,111.657 h2.54
  text "0.048mm" at 132.762,111.657 h2.54
  text "GTL" at 147.935,111.657 h2.54
  text "Dielectric 1" at 93.733,106.577 h2.54
  text "1.550mm" at 132.762,106.577 h2.54
  text "2" at 83.101,101.497 h2.54
  text "Bottom Layer" at 93.733,101.497 h2.54
  text "Copper" at 114.29,101.497 h2.54
  text "0.048mm" at 132.762,101.497 h2.54
  text "GBL" at 147.935,101.497 h2.54
  text "Bottom Solder" at 93.733,96.417 h2.54
  text "Solder Resist" at 114.29,96.417 h2.54
  text "0.030mm" at 132.762,96.417 h2.54
  text "GBS" at 147.935,96.417 h2.54
  text "Bottom Overlay" at 93.733,91.337 h2.54
  text "GBO" at 147.935,91.337 h2.54
  text "IMPEDANCE TABLE" at 37.6,88.025 h2.54
  text "Layer" at 46.6,85.452 h2.54
  text "Impedance" at 72.011,85.452 h2.54
  text "Trace" at 93.84,85.453 h2.54
  text "Trace" at 106.6,85.453 h2.54
  text "Target" at 122.6,85.453 h2.54
  text "Tolerance" at 133.6,85.453 h2.54
  text "Layer" at 147.6,85.453 h2.54
  text "Layer" at 38.6,84.452 h2.54
  text "Name" at 46.6,82.952 h2.54
  text "Structure" at 72.968,82.952 h2.54
  text "Width (µm)" at 91.757,82.953 h2.54
  text "Separation (µm)" at 103.6,82.953 h2.54
  text "Impedance" at 119.959,82.953 h2.54
  text "+/- %" at 136.356,82.953 h2.54
  text "Ref. Plane" at 145.207,82.953 h2.54
  text "106.4" at 107.45,79.475 h2.54
  text "1" at 40.6,79.452 h2.54
  text "Top Layer" at 46.6,79.452 h2.54
  text "450" at 94.86,79.446 h2.54
  text "10" at 137.492,79.453 h2.54
  text "1" at 149.833,79.453 h2.54
  text "SINGLE COPLANAR" at 68.6,79.425 h2.54
  text "50 Ohm" at 120.774,79.425 h2.54
  text "2" at 40.337,73.152 h2.54
  text "Bottom Layer" at 46.6,73.152 h2.54
Board:
  lines w0.3: 0,56.95 0,0 74,0 74,57 0,57
Drill Drawing:
  circle w0.254: c-116.309,-51.291 r1.168
  lines w0.2: -119.542,-54.036 -32.074,-54.036 ; -119.542,-38.265 -32.074,-38.265 ; -106.023,-59.293 -106.023,-33.008 ; -91.737,-59.293 -91.737,-33.008 ; -66.157,-59.293 -66.157,-33.008 ; -55.674,-59.293 -55.674,-33.008 ; -119.542,-59.293 -32.074,-59.293 -32.074,-33.008 -119.542,-33.008 -119.542,-59.293
  lines w0.254: -117.477,-44.866 -115.141,-44.866 -116.309,-47.202 -117.477,-44.866 ; -117.477,-40.777 -116.309,-41.945 -115.141,-40.777 -116.309,-39.608 -117.477,-40.777
  text "Symbol" at -116.388,-36.688 h3.05
  text "Hit Count" at -104.446,-36.688 h3.05
  text "Finished Hole Size" at -90.16,-36.688 h3.05
  text "Plated" at -64.579,-36.688 h3.05
  text "Hole Tolerance" at -54.097,-36.688 h3.05
  text "1587" at -104.446,-41.945 h2.54
  text "0.20mm (7.87mil)" at -90.16,-41.945 h2.54
  text "PTH" at -64.579,-41.945 h2.54
  text "+0.05mm/-0.10mm" at -54.097,-41.945 h2.54
  text "6" at -104.446,-47.202 h2.54
  text "0.70mm (27.56mil)" at -90.16,-47.202 h2.54
  text "PTH" at -64.579,-47.202 h2.54
  text "+0.05mm/-0.10mm" at -54.097,-47.202 h2.54
  text "65" at -104.446,-52.459 h2.54
  text "1.00mm (39.37mil)" at -90.16,-52.459 h2.54
  text "PTH" at -64.579,-52.459 h2.54
  text "+0.05mm/-0.10mm" at -54.097,-52.459 h2.54
  text "1658 Total" at -104.446,-57.716 h2.54
Top Cartridge:
  lines w0.2: -124.542,-12.943 -119.542,-12.943 ; -124.542,37.057 -114.542,37.057 ; -124.542,87.057 -119.542,87.057 ; -81.003,-64.293 -81.003,-59.293 ; -81.002,130.707 -81.002,135.707 ; -31.04,-64.293 -31.04,-59.293 ; -31.04,130.707 -31.04,135.707 ; 18.958,-64.293 18.958,-54.293 ; 18.958,125.707 18.958,135.707 ; 68.958,-64.293 68.958,-59.293 ; 68.958,130.707 68.958,135.707 ; 118.958,-64.293 118.958,-59.293 ; 118.958,130.707 118.958,135.707 ; 152.458,37.057 162.458,37.057 ; 157.458,-12.943 162.458,-12.943 ; 157.458,87.057 162.458,87.057 ; 157.458,130.707 157.458,-59.293 -119.542,-59.293 -119.542,130.707 157.458,130.707 ; -124.542,-64.293 -124.542,135.707 162.458,135.707 162.458,-64.293 -124.542,-64.293
  text "5" at 93.565,132.633 h1.85
  text "1" at -106.26,132.612 h1.85
  text "2" at -56.437,132.612 h1.85
  text "3" at -6.43,132.622 h1.85
  text "4" at 43.547,132.615 h1.85
  text "6" at 143.566,132.622 h1.85
  text "D" at -122.532,111.465 h1.85
  text "D" at 159.468,111.465 h1.85
  text "C" at -122.566,61.465 h1.85
  text "C" at 159.434,61.465 h1.85
  text "B" at -122.49,11.465 h1.85
  text "B" at 159.51,11.465 h1.85
  text "A" at -122.597,-39.886 h1.85
  text "A" at 159.403,-39.886 h1.85
  text "5" at 93.565,-62.367 h1.85
  text "1" at -106.26,-62.388 h1.85
  text "2" at -56.437,-62.388 h1.85
  text "3" at -6.43,-62.378 h1.85
  text "4" at 43.547,-62.385 h1.85
  text "6" at 143.566,-62.378 h1.85
Bottom Cartridge:
  lines w0.2: -124.542,-12.943 -119.542,-12.943 ; -124.542,37.057 -114.542,37.057 ; -124.542,87.057 -119.542,87.057 ; -119.542,130.707 -119.542,-59.293 157.458,-59.293 157.458,130.707 -119.542,130.707 ; -81.042,-64.293 -81.042,-59.293 ; -81.042,130.707 -81.042,135.707 ; -31.042,-64.293 -31.042,-59.293 ; -31.042,130.707 -31.042,135.707 ; 18.958,-64.293 18.958,-54.293 ; 18.958,125.707 18.958,135.707 ; 68.956,-64.293 68.956,-59.293 ; 68.956,130.707 68.956,135.707 ; 118.918,-64.293 118.918,-59.293 ; 118.918,130.707 118.918,135.707 ; 152.458,37.057 162.458,37.057 ; 157.458,-12.943 162.458,-12.943 ; 157.458,87.057 162.458,87.057 ; -124.542,-64.293 162.458,-64.293 162.458,135.707 -124.542,135.707 -124.542,-64.293
  text "5" at -55.649,132.633 h1.85
  text "6" at -105.65,132.622 h1.85
  text "4" at -5.631,132.615 h1.85
  text "3" at 44.345,132.622 h1.85
  text "2" at 94.352,132.612 h1.85
  text "1" at 144.176,132.612 h1.85
  text "D" at -121.553,111.465 h1.85
  text "D" at 160.447,111.465 h1.85
  text "C" at -121.518,61.465 h1.85
  text "C" at 160.482,61.465 h1.85
  text "B" at -121.594,11.465 h1.85
  text "B" at 160.406,11.465 h1.85
  text "A" at -121.488,-39.886 h1.85
  text "A" at 160.512,-39.886 h1.85
  text "5" at -55.649,-62.367 h1.85
  text "6" at -105.65,-62.378 h1.85
  text "4" at -5.631,-62.385 h1.85
  text "3" at 44.345,-62.378 h1.85
  text "2" at 94.352,-62.388 h1.85
  text "1" at 144.176,-62.388 h1.85

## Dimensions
0,0 to 0,57 on Mechanical Drawing
0,0 to 74,0 on Mechanical Drawing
